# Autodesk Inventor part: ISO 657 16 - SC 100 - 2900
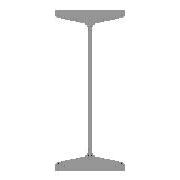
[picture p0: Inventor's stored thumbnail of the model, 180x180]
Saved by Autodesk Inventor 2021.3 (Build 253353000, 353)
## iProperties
IsCustomPart: 1
_CCFamilyMember: 1
_CCFamilyDisplayName: ISO 657/16 - 1980 - Poutres en acier laminées à chaud - Partie 16: profilés en H (série métrique) - Cotes et propriétés de section
_FrameMemberDoc: Frame Member File
_Version: 25.0.0
_GetPNFromCC: 1
Created: 2018-01
Part Number: ISO 657 16 - SC 100 - 2900
Material: Acier, doux
Description: Poutres en acier laminées à chaud - Partie 16: profilés en H (série métrique) - Cotes et propriétés de section
Document SubType Name: Modeling
Standard: ISO
Designer: Fabian Perrée
Standard Revision: First edition 1980-02-15
Standards Organization: ISO
Language: fr-FR
Size Designation: SC 100
Categories: <MemberInstance><Categories><Category DisplayName="Profilés" InternalName="089c4875-fa83-4c05-b084-43b9cc11f5ed" Mnemonic="GRDR"><CategoryParameter DisplayName=
Stock Number: SC 100
Density: 7.85 g/cm^3
Appearance: Semi-poli
Mass: 57968.8 g
Surface Area: 15748.4 cm^2
Volume: 7384.56 cm^3
G_W: 100,000 mm
G_H: 100,000 mm
+7C75FE93-44B4-4967-A4EC-28715C0C1D86+DETAILDECOUPE1: Angle de coupe 90,00 deg
G_L: 2900,000 mm
Author: Fabian Perrée
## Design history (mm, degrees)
node "Plan de départ"
node "Plan de fin"
sketch "Esquisse"
  geometry: L1 (-3, 0)-(-3, -26.266); L2 (-13.33, -38.149)-(-44.835, -42.577); L3 (-50, -48.518)-(-50, -50); L4 (-50, -50)-(0, -50); L5 (-26.5, -50)-(-26.5, -40); L6 (-61.333, 0)-(81.777, 0); L7 (0, 0)-(0, -50); L8 (0, -60)-(0, 80); L9 (3, 0)-(3, -26.266); L10 (13.33, -38.149)-(44.835, -42.577); L11 (50, -48.518)-(50, -50); L12 (50, -50)-(0, -50); L13 (-3, 0)-(0, 0); L14 (-3, 0)-(-3, 26.266); L15 (-13.33, 38.149)-(-44.835, 42.577); L16 (-50, 48.518)-(-50, 50); L17 (-50, 50)-(0, 50); L18 (50, 48.518)-(50, 50); L19 (13.33, 38.149)-(44.835, 42.577); L20 (3, 0)-(3, 26.266); L21 (50, 50)-(0, 50); L22 (0, 108)-(0, -88) reference; L23 (-89.955, 0)-(110.399, 0) reference; A1 r 6 centre (-44, 48.518) between (-50, 48.518) and (-44.835, 42.577); A2 r 6 centre (44, 48.518) between (44.835, 42.577) and (50, 48.518); A3 r 6 centre (44, -48.518) between (50, -48.518) and (44.835, -42.577); A4 r 6 centre (-44, -48.518) between (-44.835, -42.577) and (-50, -48.518); A5 r 12 centre (-15, 26.266) between (-3, 26.266) and (-13.33, 38.149); A6 r 12 centre (15, 26.266) between (13.33, 38.149) and (3, 26.266); A7 r 12 centre (15, -26.266) between (3, -26.266) and (13.33, -38.149); A8 r 12 centre (-15, -26.266) between (-13.33, -38.149) and (-3, -26.266); 14 further points
  constraints: 42 end point, 24 point on line, 17 symmetric about line, 16 point on circle, 16 tangent, 8 centre point, 6 equal radius, 4 collinear, 2 perpendicular, 12 other
  dimensions: "d1" = 10 vertical distance of L3.end L5.end (= G_T1); "d2" = 23.5 distance between parallel lines of L5 L3 (= -0.25 x G_T + 0.25 x G_W); "d3" = 3 distance between parallel lines of L1 L7 (= 0.5 x G_T); "d4" = 50 distance between parallel lines of L7 L3 (= 0.5 x G_W); "d9" = 50 distance from line of L1.start L4 (= 0.5 x G_H); "d14" = 98 deg angle of L2 L1 (= G_NG); "d15" = 6 radius of A1 (= G_ER); "d16" = 12 radius of A5 (= G_IR)
extrude "Corps" new body sketch "Esquisse" stored distance "d5" = 2900 (= G_L); taper "d6" = 0 deg
node "Driven Length"
  sketch "Sketch3"
    geometry: L1 (0, 0)-(10, 0) reference
    constraints: 2 end point, 1 horizontal
  workplane "Work Plane3"
  sketch "Sketch4"
    geometry: L1 (-2, 0)-(12, 0) reference; L2 (-2, 2900)-(12, 2900) reference
    dimensions: "d20" = 2900 distance between parallel lines of L1 L2 (derived)
node "Plan de construction4"
feature "Scission1"
body "Solid1"
other parameters: "G_W" = 100 (= G_H) [user parameter; used in 2 equation terms], "G_H" = 100 [user parameter; used in 2 equation terms], "G_T" = 6 [user parameter; used in 2 equation terms], "G_T1" = 10 [user parameter; used in 1 equation term], "G_L" = 2900 (= d20) [user parameter; used in 1 equation term], "G_ER" = 6 [user parameter; used in 1 equation term], "G_IR" = 12 [user parameter; used in 1 equation term], "G_NG" = 98 deg [user parameter; used in 1 equation term], "G_OFFSET_START" = 0 [user parameter; used in 1 equation term], "d17" = 0 (computed from G_OFFSET_START), "d19" = 90 deg
